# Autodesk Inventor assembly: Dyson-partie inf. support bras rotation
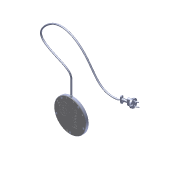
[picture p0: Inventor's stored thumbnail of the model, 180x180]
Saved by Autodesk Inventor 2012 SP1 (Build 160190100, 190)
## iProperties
Created: 2012-11
Part Number: Dyson-partie inf. support bras rotation
Document SubType Name: Assembly
Designer: Administrateur
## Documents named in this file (11)
- D:\Cours\1-Cours-2013-14\Dropbox\1SI\1. Besoin\Dyson\Composants importés\Dyson Air Multiplier-Assemblage final\Dyson-partie inf. support bras rotation.iam
- D:\Cours\1-Cours-2013-14\Dropbox\1SI\1. Besoin\Dyson\Composants importés\Dyson Air Multiplier-Assemblage final\Dyson-Partie inf. base ABS marron.ipt
- D:\Cours\1-Cours-2013-14\Dropbox\1SI\1. Besoin\Dyson\Composants importés\Dyson Air Multiplier-Assemblage final\Dyson-Partie inf. base grise clair.ipt
- D:\Cours\1-Cours-2013-14\Dropbox\1SI\1. Besoin\Dyson\Composants importés\Dyson Air Multiplier-Assemblage final\Vis torks M2x6.ipt
- D:\Cours\1-Cours-2013-14\Dropbox\1SI\1. Besoin\Dyson\Composants importés\Dyson Air Multiplier-Assemblage final\Dyson-Partie inf. tampon.ipt
- D:\Cours\1-Cours-2013-14\Dropbox\1SI\1. Besoin\Dyson\Composants importés\Dyson Air Multiplier-Assemblage final\Dyson-Partie inf.axe bielle 1.ipt
- D:\Cours\1-Cours-2013-14\Dropbox\1SI\1. Besoin\Dyson\Composants importés\Dyson Air Multiplier-Assemblage final\Circlps Ø3 int.ipt
- D:\Cours\1-Cours-2013-14\Dropbox\1SI\1. Besoin\Dyson\Composants importés\Dyson Air Multiplier-Assemblage final\Dyson-Partie inf.bielle plastique.ipt
- D:\Cours\1-Cours-2013-14\Dropbox\1SI\1. Besoin\Dyson\Composants importés\Dyson Air Multiplier-Assemblage final\Dyson-Partie inf.axe bielle 2.ipt
- D:\Cours\1-Cours-2013-14\Dropbox\1SI\1. Besoin\Dyson\Composants importés\Dyson Air Multiplier-Assemblage final\Dyson-Partie inf.bielle acier.ipt
- D:\Cours\1-Cours-2013-14\Dropbox\1SI\1. Besoin\Dyson\Composants importés\Dyson Air Multiplier-Assemblage final\Dyson-Partie inf. cablage prise.ipt
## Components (20 placed, 10 different names)
1. Dyson-Partie inf. base ABS marron:1
2. Dyson-Partie inf. base grise clair:1 — Placage:1, Placage:2
3. Vis torks M2x6:1
4. Vis torks M2x6:2
5. Vis torks M2x6:3
6. Vis torks M2x6:4
7. Vis torks M2x6:5
8. Dyson-Partie inf. tampon:1
9. Dyson-Partie inf. tampon:6
10. Dyson-Partie inf. tampon:7
11. Dyson-Partie inf. tampon:8
12. Dyson-Partie inf. tampon:9
13. Dyson-Partie inf.axe bielle 1:1 — Logement:1, Logement:2, Logement:3
14. Circlps Ø3 int:1 — Logement:1
15. Circlps Ø3 int:2 — Logement:3
16. Dyson-Partie inf.bielle plastique:2 — Logement:6
17. Dyson-Partie inf.axe bielle 2:1 — Logement:4, Logement:5
18. Circlps Ø3 int:3 — Logement:5
19. Dyson-Partie inf.bielle acier:1 — Logement:2, Logement:4, Logement:6
20. Dyson-Partie inf. cablage prise:1 — Placage:1, Placage:2
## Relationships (8: Insert 6, Mate 2)
- Placage:1 [Mate]: Dyson-Partie inf. base grise clair:1 ↔ Dyson-Partie inf. cablage prise:1
- Placage:2 [Mate]: Dyson-Partie inf. base grise clair:1 ↔ Dyson-Partie inf. cablage prise:1
- Logement:1 [Insert]: Dyson-Partie inf.axe bielle 1:1 ↔ Circlps Ø3 int:1
- Logement:2 [Insert]: Dyson-Partie inf.axe bielle 1:1 ↔ Dyson-Partie inf.bielle acier:1
- Logement:3 [Insert]: Dyson-Partie inf.axe bielle 1:1 ↔ Circlps Ø3 int:2
- Logement:4 [Insert]: Dyson-Partie inf.axe bielle 2:1 ↔ Dyson-Partie inf.bielle acier:1
- Logement:5 [Insert]: Dyson-Partie inf.axe bielle 2:1 ↔ Circlps Ø3 int:3
- Logement:6 [Insert]: Dyson-Partie inf.bielle plastique:2 ↔ Dyson-Partie inf.bielle acier:1
